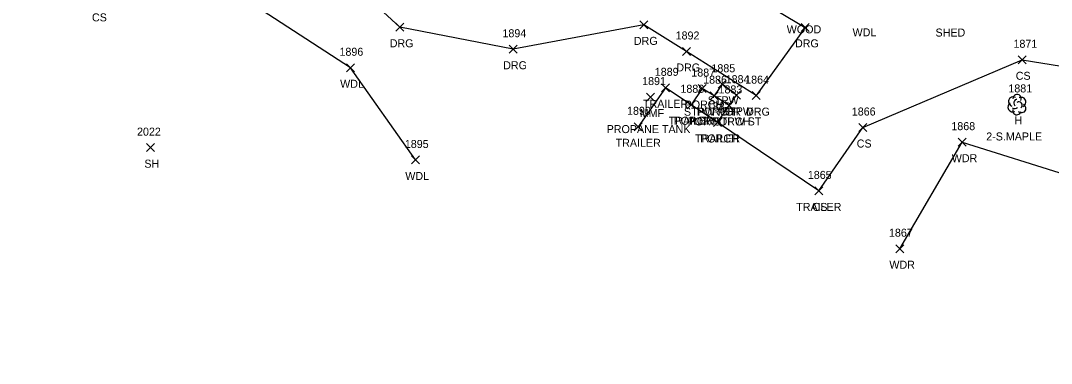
# Model space of a CAD drawing. Extents: x 1477930 to 1480780, y 774090 to 784647.
# Drawn here: x 1478912.6 to 1479170.3, y 774292.7 to 774378.4 of the extents above; entities that cross this region are included whole.
import ezdxf

# ---------------------------------------------------------------- set-up
doc = ezdxf.new("R2010")
doc.units = 0
for name, color, linetype in [('L_A', 7, 'Continuous'), ('L_C', 7, 'Continuous'), ('L_I', 7, 'Continuous'), ('L_TIC', 7, 'Continuous'), ('LAWA', 7, 'Continuous'), ('LBC', 7, 'Continuous'), ('LBF', 7, 'Continuous'), ('LELB', 7, 'Continuous'), ('LTD', 7, 'Continuous'), ('R_A', 7, 'Continuous'), ('R_C', 7, 'Continuous'), ('R_I', 7, 'Continuous'), ('R_TIC', 7, 'Continuous'), ('RDG', 7, 'Continuous')]:
    doc.layers.add(name, color=color, linetype=linetype)

msp = doc.modelspace()

# ---------------------------------------------------------------- linework, layer by layer
at = {"layer": 'L_TIC'}
for points in [[(1479161.97, 774367.59), (1479163.97, 774369.59)], [(1479163.97, 774367.59), (1479161.97, 774369.59)], [(1478994.1, 774365.59), (1478996.1, 774367.59)], [(1478996.1, 774365.59), (1478994.1, 774367.59)], [(1479087.02, 774361.47), (1479089.02, 774363.47)], [(1479089.02, 774361.47), (1479087.02, 774363.47)], [(1479072.87, 774360.58), (1479074.87, 774362.58)], [(1479074.87, 774360.58), (1479072.87, 774362.58)], [(1479082.01, 774360.4), (1479084.01, 774362.4)], [(1479084.01, 774360.4), (1479082.01, 774362.4)], [(1479085.01, 774358.61), (1479087.01, 774360.61)], [(1479087.01, 774358.61), (1479085.01, 774360.61)], [(1479085.01, 774358.61), (1479087.01, 774360.61)], [(1479087.01, 774358.61), (1479085.01, 774360.61)], [(1479090.58, 774358.74), (1479092.58, 774360.74)], [(1479092.58, 774358.74), (1479090.58, 774360.74)], [(1479069.14, 774358.27), (1479071.14, 774360.27)], [(1479071.14, 774358.27), (1479069.14, 774360.27)], [(1479079.27, 774356.34), (1479081.27, 774358.34)], [(1479081.27, 774356.34), (1479079.27, 774358.34)], [(1479079.27, 774356.34), (1479081.27, 774358.34)], [(1479081.27, 774356.34), (1479079.27, 774358.34)], [(1479088.79, 774356.18), (1479090.79, 774358.18)], [(1479090.79, 774356.18), (1479088.79, 774358.18)], [(1479088.79, 774356.18), (1479090.79, 774358.18)], [(1479090.79, 774356.18), (1479088.79, 774358.18)], [(1479066.02, 774350.84), (1479068.02, 774352.84)], [(1479068.02, 774350.84), (1479066.02, 774352.84)], [(1479085.88, 774351.92), (1479087.88, 774353.92)], [(1479087.88, 774351.92), (1479085.88, 774353.92)], [(1479085.88, 774351.92), (1479087.88, 774353.92)], [(1479087.88, 774351.92), (1479085.88, 774353.92)], [(1479122.22, 774350.66), (1479124.22, 774352.66)], [(1479124.22, 774350.66), (1479122.22, 774352.66)], [(1478944.08, 774345.63), (1478946.08, 774347.63)], [(1478946.08, 774345.63), (1478944.08, 774347.63)], [(1479147.05, 774347), (1479149.05, 774349)], [(1479149.05, 774347), (1479147.05, 774349)], [(1479010.38, 774342.55), (1479012.38, 774344.55)], [(1479012.38, 774342.55), (1479010.38, 774344.55)], [(1479111.17, 774334.82), (1479113.17, 774336.82)], [(1479113.17, 774334.82), (1479111.17, 774336.82)], [(1479111.17, 774334.82), (1479113.17, 774336.82)], [(1479113.17, 774334.82), (1479111.17, 774336.82)], [(1479131.45, 774320.38), (1479133.45, 774322.38)], [(1479133.45, 774320.38), (1479131.45, 774322.38)]]:
    msp.add_lwpolyline(points, dxfattribs=at)
at = {"layer": 'LAWA'}
for points in [[(1479011.38, 774343.55), (1478995.1, 774366.59), (1478968.24, 774384.07), (1478947.58, 774395.67), (1478961.25, 774413.39), (1478952.73, 774420.76), (1478901.61, 774417.12), (1478856.8, 774391.87), (1478808.81, 774377.19), (1478801.18, 774332.41), (1478792.3, 774292.73)], [(1479132.45, 774321.38), (1479148.05, 774348), (1479175.1, 774339.47), (1479202.22, 774329.33)]]:
    msp.add_lwpolyline(points, dxfattribs=at)
at = {"layer": 'LBC'}
msp.add_lwpolyline([(1479112.17, 774335.82), (1479086.88, 774352.92), (1479080.27, 774357.34), (1479073.87, 774361.58), (1479067.02, 774351.84)], dxfattribs=at)
at = {"layer": 'LBF'}
for points in [[(1479086.88, 774352.92), (1479089.79, 774357.18), (1479086.01, 774359.61), (1479083.01, 774361.4), (1479080.27, 774357.34)], [(1479089.79, 774357.18), (1479091.58, 774359.74), (1479088.02, 774362.47), (1479086.01, 774359.61)]]:
    msp.add_lwpolyline(points, dxfattribs=at)
at = {"layer": 'LELB'}
msp.add_lwpolyline([(1479112.17, 774335.82), (1479123.22, 774351.66), (1479162.97, 774368.59), (1479187.33, 774364.69), (1479202.58, 774354.26)], dxfattribs=at)
at = {"layer": 'LTD'}
msp.add_line((1479161.68, 774357.43), (1479161.68, 774357.43), dxfattribs=at)
msp.add_line((1479161.68, 774357.43), (1479161.68, 774357.43), dxfattribs=at)
msp.add_arc((1479161.73, 774358.87), 1.05, 335.5272, 180.9563, dxfattribs=at)
for centre, major_axis, ratio, start_param, end_param in [((1479160.89, 774358.1), (1.21, -0.51), 0.895232, 1.570796, 4.712389), ((1479161.48, 774357.89), (-0.208, -0.792), 0.645439, 3.141593, 6.283185), ((1479162.18, 774357.27), (-0.5, 0.667), 0.989748, 3.141593, 6.283185), ((1479162.73, 774358.02), (-1.14, -0.48), 0.949671, 1.570796, 4.712389), ((1479160.6, 774356.73), (0.58, -1.04), 0.959034, 3.141593, 6.283185), ((1479161.68, 774355.93), (0.26, 1.06), 0.942809, 1.570796, 4.712389), ((1479161.23, 774356.68), (-0.625, -0.083), 0.423636, 0, 3.141593), ((1479162.68, 774356.6), (-1.09, 0.79), 0.841452, 1.570796, 4.712389)]:
    msp.add_ellipse(centre, major_axis=major_axis, ratio=ratio, start_param=start_param, end_param=end_param, dxfattribs=at)
at = {"layer": 'R_TIC'}
for points in [[(1479006.43, 774375.71), (1479008.43, 774377.71)], [(1479008.43, 774375.71), (1479006.43, 774377.71)], [(1479067.45, 774376.31), (1479069.45, 774378.31)], [(1479069.45, 774376.31), (1479067.45, 774378.31)], [(1479107.74, 774375.69), (1479109.74, 774377.69)], [(1479109.74, 774375.69), (1479107.74, 774377.69)], [(1479034.79, 774370.22), (1479036.79, 774372.22)], [(1479036.79, 774370.22), (1479034.79, 774372.22)], [(1479078.07, 774369.66), (1479080.07, 774371.66)], [(1479080.07, 774369.66), (1479078.07, 774371.66)], [(1479095.51, 774358.63), (1479097.51, 774360.63)], [(1479097.51, 774358.63), (1479095.51, 774360.63)]]:
    msp.add_lwpolyline(points, dxfattribs=at)
at = {"layer": 'RDG'}
msp.add_lwpolyline([(1479000.29, 774404.19), (1479014.66, 774390.05), (1479047.46, 774386.41), (1479082.42, 774397.91), (1479092.78, 774404.14), (1479080.31, 774426.66), (1479099.49, 774435.86), (1479111.25, 774415.08), (1479119.41, 774407.6), (1479089.11, 774388.5), (1479108.74, 774376.69), (1479096.51, 774359.63), (1479079.07, 774370.66), (1479068.45, 774377.31), (1479035.79, 774371.22), (1479007.43, 774376.71), (1478987.91, 774394.73)], dxfattribs=at)

# ---------------------------------------------------------------- texts
at = {"layer": 'L_A'}
for s, p in [('CS', (1478930.48, 774378.18)), ('WDL', (1479120.61, 774374.44)), ('SHED', (1479141.35, 774374.39)), ('CS', (1479161.41, 774363.59)), ('WDL', (1478992.52, 774361.59)), ('TRAILER', (1479068.23, 774356.58)), ('PORCH', (1479078.63, 774356.4)), ('STPW', (1479084.41, 774357.47)), ('MMF', (1479067.42, 774354.27)), ('STPW POR', (1479078.46, 774354.61)), ('PORCH', (1479081.63, 774354.61)), ('STPW', (1479087.98, 774354.74)), ('TRAILER', (1479074.63, 774352.34)), ('PORCH', (1479075.89, 774352.34)), ('POR STPW ST', (1479079.38, 774352.18)), ('PORCH', (1479085.42, 774352.18)), ('H', (1479161.12, 774352.43)), ('TRAILER', (1479061.38, 774346.84)), ('TRAILER', (1479081.24, 774347.92)), ('PORCH', (1479082.5, 774347.92)), ('CS', (1479121.66, 774346.66)), ('WDR', (1479145.41, 774343)), ('SH', (1478943.57, 774341.63)), ('WDL', (1479008.8, 774338.55)), ('TRAILER', (1479106.53, 774330.82)), ('CS', (1479110.61, 774330.82)), ('WDR', (1479129.81, 774316.38))]:
    msp.add_text(s, height=2, dxfattribs=at).set_placement(p)
at = {"layer": 'L_C'}
for s, p in [('PROPANE TANK', (1479059.14, 774350.27)), ('2-S.MAPLE', (1479154.03, 774348.43))]:
    msp.add_text(s, height=2, dxfattribs=at).set_placement(p)
at = {"layer": 'L_I'}
for s, p in [('1871', (1479160.84, 774371.59)), ('1896', (1478992.35, 774369.59)), ('1889', (1479071.17, 774364.58)), ('1887', (1479080.31, 774364.4)), ('1885', (1479085.33, 774365.47)), ('1891', (1479068.01, 774362.27)), ('1886', (1479083.26, 774362.61)), ('1886', (1479083.26, 774362.61)), ('1884', (1479088.89, 774362.74)), ('1888', (1479077.58, 774360.34)), ('1888', (1479077.58, 774360.34)), ('1883', (1479087.1, 774360.18)), ('1883', (1479087.1, 774360.18)), ('1881', (1479159.56, 774360.43)), ('1882', (1479084.19, 774355.92)), ('1882', (1479084.19, 774355.92)), ('1890', (1479064.24, 774354.84)), ('1866', (1479120.42, 774354.66)), ('1868', (1479145.31, 774351)), ('2022', (1478941.74, 774349.63)), ('1895', (1479008.69, 774346.55)), ('1865', (1479109.43, 774338.82)), ('1865', (1479109.43, 774338.82)), ('1867', (1479129.71, 774324.38))]:
    msp.add_text(s, height=2, dxfattribs=at).set_placement(p)
at = {"layer": 'R_A'}
for p in [(1479004.91, 774371.71), (1479065.94, 774372.31), (1479106.22, 774371.69), (1479033.27, 774366.22), (1479076.56, 774365.66), (1479094, 774354.63)]:
    msp.add_text('DRG', height=2, dxfattribs=at).set_placement(p)
at = {"layer": 'R_C'}
msp.add_text('WOOD', height=2, dxfattribs=at).set_placement((1479104.16, 774375.19))
at = {"layer": 'R_I'}
for s, p in [('1894', (1479033.09, 774374.22)), ('1892', (1479076.38, 774373.66)), ('1864', (1479093.77, 774362.63))]:
    msp.add_text(s, height=2, dxfattribs=at).set_placement(p)

doc.saveas('drawing.dxf')
